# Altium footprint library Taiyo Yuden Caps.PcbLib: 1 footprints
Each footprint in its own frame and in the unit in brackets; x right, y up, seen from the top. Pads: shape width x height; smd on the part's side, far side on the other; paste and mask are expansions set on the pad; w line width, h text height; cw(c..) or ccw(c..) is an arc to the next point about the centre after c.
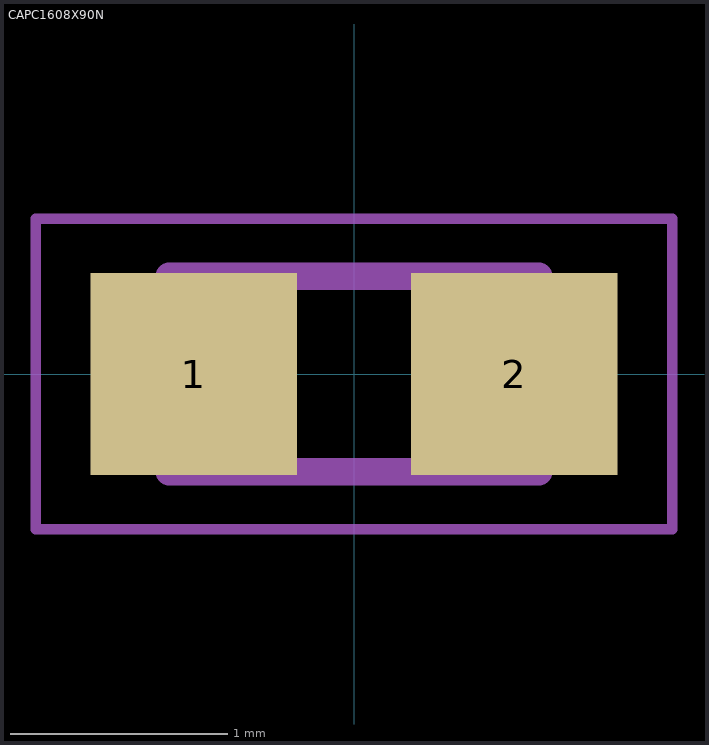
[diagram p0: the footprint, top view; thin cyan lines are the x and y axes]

## CAPC1608X90N [mm]
pads (2):
  rect 0.95x0.93 smd: 1(-0.738,0) 2(0.738,0)
Mechanical 13:
  lines w0.127: -0.85,-0.45 0.85,-0.45 0.85,0.45 -0.85,0.45 -0.85,-0.45
Mechanical 15:
  lines w0.05: -1.465,-0.715 1.465,-0.715 1.465,0.715 -1.465,0.715 -1.465,-0.715
3D body "0603 capacitors.STEP": height 0.41, standoff -0.41, extent -0.738,-0.45 0.862,0.45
